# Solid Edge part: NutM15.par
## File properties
Author: ptcarter
Template: NORMAL.PAR
Last saved by: ptcarter
Revision: 38
Application: Solid Edge
Accuracy: 0.99
File Size: 0
Number of Sheets: 0
Number of Objects: 0
Document Number: NutM15
Material: steel
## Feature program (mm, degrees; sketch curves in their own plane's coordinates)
sketch for "unnamed Protrusion 1" plane through (0, 0, 0) normal (0, 0, 1) x-axis (1, 0, 0)
  line (-6.9282, -12) -> (6.9282, -12)
  line (6.9282, -12) -> (13.8564, 0)
  line (13.8564, 0) -> (6.9282, 12)
  line (6.9282, 12) -> (-6.9282, 12)
  line (-6.9282, 12) -> (-13.8564, 0)
  line (-13.8564, 0) -> (-6.9282, -12)
extrude "unnamed Protrusion 1" add finite 7.5 along +normal
sketch for "unnamed RevolvedCutout 1" plane through (0, 0, 0) normal (0, -1, 0) x-axis (1, 0, 0)
  line (-15.1213, 4.5223) -> (-10.8787, 8.7649)
  line (-10.8787, 8.7649) -> (-19.9377, 8.7649)
  line (-19.9377, 8.7649) -> (-19.9377, -1.2649)
  line (-19.9377, -1.2649) -> (-10.8787, -1.2649)
  line (-15.1213, 2.9777) -> (-10.8787, -1.2649)
  line (-15.1213, 2.9777) -> (-15.1213, 4.5223)
revolve "unnamed RevolvedCutout 1" cut full turn 360 deg
sketch for "unnamed Cutout 1" plane through (0, 0, 0) normal (0, 0, -1) x-axis (1, 0, 0)
  circle centre (0, 0) radius 7.5
extrude "unnamed Cutout 1" cut through along -normal
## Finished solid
Body 1: solid body, 21 faces, 56 edges, 36 vertices.
  Faces by surface: cone 12, plane 8, cylinder 1
  Edges by curve: intersection 24, line 18, circle 14
Bounding box of the edges (mm): 27.713 x 24.000 x 7.500, from (-13.8564, -12, 0) to (13.8564, 12, 7.5).
Cylindrical faces by radius (mm): R7.5 x1
Conical faces (half-angle, radius in mm at the cone's reference point): 45 deg R10.8787 x6, 45 deg R15.1213 x6
Planar faces by outward normal: +y 1, +z 1, -y 1, -z 1, oblique 4
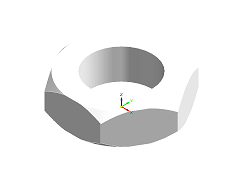
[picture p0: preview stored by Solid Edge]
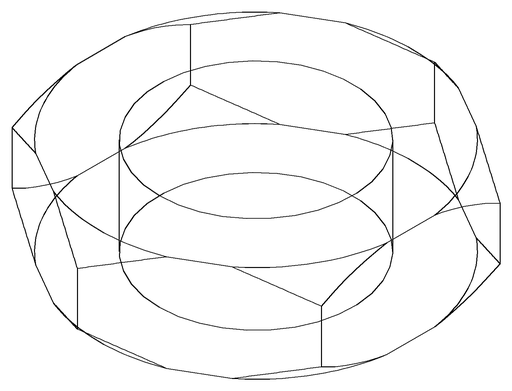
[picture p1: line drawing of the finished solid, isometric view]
